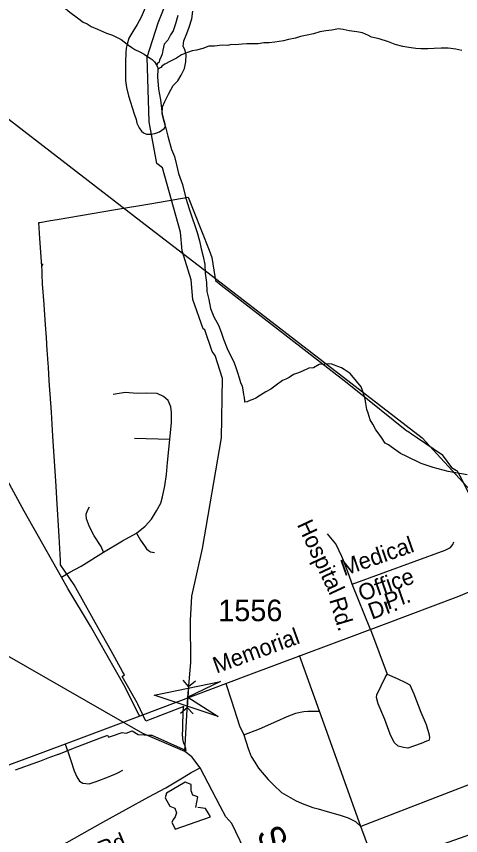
# Model space of a CAD drawing. Extents: x 2260773 to 2342389, y 552869 to 618546.
# Drawn here: x 2309864 to 2312438, y 601248 to 605993 of the extents above; entities that cross this region are included whole.
import ezdxf

# ---------------------------------------------------------------- set-up
doc = ezdxf.new("R2010")
doc.units = 0
for name, color, linetype in [('Exist Boundary Political City Limit New', 7, 'Continuous'), ('Exist Hydrographic Creek Single Shore', 7, 'Continuous'), ('Exist Hydrographic Creek Single Shore Label', 7, 'Continuous'), ('Exist Hydrographic Misc Water Feature', 7, 'Continuous'), ('Exist Road Non-System Type 51', 7, 'Continuous'), ('Exist Road Non-System Type 51 Label', 7, 'Continuous'), ('Exist Road Secondary Structure Culvert Attributed CELL', 7, 'Continuous'), ('Exist Road Secondary Structure Culvert CELL', 7, 'Continuous'), ('Exist Road Secondary Type 51 Attributed', 7, 'Continuous'), ('Exist Road Secondary Type 51 Label', 7, 'Continuous'), ('Exist Road Secondary Type 51 Number Label', 7, 'Continuous'), ('Exist Road Secondary Type 51 Undivided 4 Lane Attributed', 7, 'Continuous'), ('Exist Utilities Electrical Transmission Line', 7, 'Continuous'), ('Map Preparation Boundary City Limit Buffer Line', 7, 'Continuous')]:
    doc.layers.add(name, color=color, linetype=linetype)

msp = doc.modelspace()

# ---------------------------------------------------------------- linework, layer by layer
at = {"layer": 'Exist Boundary Political City Limit New'}
for points in [[(2310013.5, 604550.2), (2310011, 604546.4), (2310000, 604706.4), (2309994, 604798.9), (2310000, 604799.9), (2310061.2, 604810.6), (2310100, 604817.1), (2310235.5, 604839.6), (2310247.5, 604841.6), (2310426.2, 604871.9), (2310649.5, 604909.8), (2310859.5, 604945.5), (2310892, 604862.9), (2310980.5, 604639.3), (2310997.2, 604596.9), (2311014.8, 604486.6), (2311018.5, 604462.6), (2311051.5, 604437), (2311762.8, 603884.8), (2311828.8, 603832.5), (2312117.2, 603600.2), (2312127, 603592.4), (2312131, 603589.9), (2312153.8, 603574.3), (2312188.2, 603551.1), (2312326, 603457.9), (2312329, 603454.9), (2312337.5, 603446.2), (2312385.8, 603381.1), (2312414.8, 603362.3), (2312418.2, 603360.1), (2312426, 603344.6), (2312432.5, 603332), (2312491.2, 603218.5)], [(2310013.5, 604550.2), (2310015, 604555.2), (2310016, 604559.1), (2310016.2, 604559.6)], [(2310016.2, 604559.6), (2310016, 604559.1), (2310015, 604555.2), (2310013.5, 604550.2)], [(2310011, 604541.6), (2310013.5, 604550.2)], [(2310648, 601830.8), (2310848.5, 601742.1), (2310846.8, 601749.4), (2310846, 601754.9), (2310844.2, 601758.4), (2310843.2, 601761.3), (2310842.5, 601764.1), (2310841.5, 601767), (2310840.5, 601769.7), (2310838.8, 601773.4), (2310837.5, 601776.2), (2310836.5, 601778.9), (2310835.2, 601781.7), (2310834.2, 601784.6), (2310833, 601788.3), (2310831.8, 601792.2), (2310831, 601795.1), (2310830.5, 601798.1), (2310830, 601802), (2310829.5, 601805.9), (2310829.2, 601809.4), (2310828.8, 601813.9), (2310828.2, 601817.9), (2310828, 601821.3), (2310827.5, 601826.9), (2310827.2, 601831.4), (2310826.8, 601838.5), (2310827.2, 601843.8), (2310827.5, 601847.8), (2310827.8, 601851.3), (2310828, 601854.8), (2310828.5, 601857.8), (2310828.8, 601861.2), (2310829.2, 601865.2), (2310829.2, 601871.7), (2310829, 601875.7), (2310829, 601879.2), (2310828.8, 601883.7), (2310828.5, 601886.7), (2310828.2, 601893.6), (2310828.5, 601898.7), (2310828.8, 601901.7), (2310829, 601906.3), (2310829, 601909.8), (2310829.2, 601914.7), (2310829.5, 601918.6), (2310829.5, 601922.5), (2310830, 601927.6), (2310830.2, 601931.3), (2310830.5, 601934.2), (2310830.5, 601950.1), (2310830.2, 601953.6), (2310830, 601957.6), (2310830, 601965.6), (2310830.2, 601969.6), (2310830.8, 601975.8), (2310831.5, 601981.5), (2310831.8, 601984.4), (2310832.2, 601987.4), (2310832.5, 601990.9), (2310835, 601996), (2310614, 601912.1), (2310567.8, 602008.9), (2310565.8, 602012.9), (2310563.8, 602016.4), (2310477, 602170.6), (2310491.5, 602178.8), (2310480, 602199.1), (2310413.5, 602318), (2310339, 602450.8), (2310311.8, 602500), (2310198.8, 602701.3), (2310119.2, 602815.7), (2310119.8, 602842.4), (2310111.2, 602980.9), (2310098.2, 603200.6), (2310094, 603271.3), (2310087, 603387.8), (2310076, 603561.8), (2310067.2, 603700.3), (2310063.8, 603751.8), (2310055, 603882.5), (2310049.8, 603960.8), (2310046.8, 604008.2), (2310044.8, 604039.1), (2310043.2, 604058.4), (2310038, 604132.7), (2310033, 604205.7), (2310026.8, 604292.6), (2310026.5, 604297.1), (2310024.8, 604321), (2310024.5, 604324), (2310016.5, 604444), (2310013, 604497.9), (2310012.8, 604522.5), (2310011, 604541.6)], [(2309859.2, 601628.8), (2309987.8, 601675.7), (2310000, 601680.2), (2310059, 601702.8), (2310102.2, 601719.1), (2310106, 601720.2), (2310110, 601720.6), (2310196, 601754.8), (2310215.2, 601762.2), (2310221, 601764.3), (2310351.8, 601813.8), (2310388.5, 601827.7), (2310393, 601829.3), (2310397.5, 601818.5), (2310414.5, 601824.3), (2310477.2, 601845.9), (2310499.8, 601841.6), (2310535.5, 601854.5), (2310570.2, 601834.4), (2310571, 601834.4), (2310637.2, 601830.9), (2310648, 601830.8)]]:
    msp.add_lwpolyline(points, dxfattribs=at)
at = {"layer": 'Exist Hydrographic Creek Single Shore'}
for points in [[(2310839.2, 601735), (2310858.2, 602050.4), (2310875.4, 602251.7), (2310873.2, 602494.4), (2310880.2, 602635.8), (2310943.1, 602910.7), (2311053, 603551.8), (2311058.2, 603896.5), (2311015.1, 604029.3), (2310998.1, 604051.6), (2310955.2, 604177.9), (2310946.2, 604184), (2310886.1, 604352.3), (2310877.1, 604466.7), (2310825.2, 604635.3), (2310815.2, 604743.1), (2310711.2, 605116.3), (2310678.2, 605141.3), (2310633.1, 605382.3), (2310621.2, 605755.9), (2310686.2, 605955.4), (2310953.2, 606625.8)], [(2310839.2, 601735), (2310597.2, 601840), (2309381, 602535.8), (2308987.1, 602831.6), (2308768.1, 603019.6), (2308156.1, 603398.5), (2307938.1, 603570.1), (2307803.2, 603702.5), (2307559.2, 603997.8), (2307415, 604156.1), (2307246, 604379), (2307178.2, 604510.7), (2307169.1, 604579.3), (2307110.1, 604668.8), (2307110.1, 604701.6), (2307093.1, 604727.1), (2307092, 604760), (2307067, 604785.2), (2307040, 604925.2)], [(2311990.9, 599754.9), (2311893.3, 599852.6), (2311820.6, 599965.6), (2311751.1, 600126.2), (2311638.5, 600351.5), (2311550.9, 600489.2), (2311457.1, 600689.5), (2311206.8, 601121.4), (2311112.6, 601319.4), (2311078.4, 601357), (2311044.3, 601418.4), (2310928.3, 601640.4), (2310881.2, 601703.9), (2310839.2, 601735)]]:
    msp.add_lwpolyline(points, dxfattribs=at)
at = {"layer": 'Exist Hydrographic Misc Water Feature'}
msp.add_line((2310728, 605353.5), (2310725.6, 605363.2), dxfattribs=at)
for points in [[(2310914.8, 606896.4), (2310899.2, 606862.3), (2310879.8, 606814.1), (2310856.4, 606765.7), (2310833, 606701.5), (2310800, 606633.5), (2310776.6, 606549), (2310767.6, 606489.2), (2310745.9, 606421), (2310738.9, 606362.9), (2310703.8, 606282.6), (2310690.1, 606238.4), (2310669, 606180), (2310643.3, 606123.8), (2310628, 606081.9), (2310615.9, 606055.8), (2310587.2, 605987.5), (2310563.6, 605945.3), (2310538.2, 605904.9), (2310516.4, 605866.8), (2310506.6, 605832.6)], [(2309889.2, 606377.7), (2309917.7, 606334), (2309963.8, 606274.8), (2310014.9, 606221.3), (2310041.1, 606189.4), (2310073.7, 606135.8), (2310110, 606086.1), (2310136.7, 606048.5), (2310174.8, 606017.1), (2310219.3, 605983.3), (2310251.5, 605959.8), (2310273.6, 605950), (2310297.8, 605934.5), (2310333.9, 605918.6), (2310386, 605895.3), (2310421.9, 605883.8), (2310470.5, 605858.3), (2310506.6, 605832.6)], [(2310798.8, 605997.8), (2310785.2, 605949.6), (2310771.7, 605909.4), (2310758, 605885.1), (2310742.4, 605855), (2310720.4, 605830.8), (2310712.7, 605797.1), (2310709.2, 605772.9), (2310703.2, 605760.8), (2310693.6, 605738.7), (2310691.7, 605726.8), (2310679.6, 605718.5), (2310678, 605708.6)], [(2310845.1, 605780.4), (2310840.8, 605798), (2310830.6, 605820.3), (2310834.7, 605850.1), (2310851.7, 605894.1), (2310865.4, 605930.6), (2310880.6, 605978.6), (2310886.3, 606022.8)], [(2312443.9, 605795.6), (2312409.9, 605803.2), (2312366.2, 605808.5), (2312325.8, 605808.1), (2312284.2, 605805.8), (2312247.9, 605805.2), (2312207.9, 605804.7), (2312178, 605806.8), (2312138.2, 605812), (2312102.1, 605817.8), (2312057.6, 605829.4), (2312019.4, 605844.9), (2311965.9, 605862.3), (2311921.4, 605871.8), (2311903.2, 605881.8), (2311869.1, 605897.1), (2311837, 605902.8), (2311791.2, 605908.5), (2311757.2, 605916), (2311731.1, 605919.9), (2311691.4, 605913.3), (2311656.9, 605908.8), (2311621.4, 605902.4), (2311585.4, 605892.4), (2311549.5, 605884), (2311509.9, 605875.4), (2311481.6, 605867), (2311440, 605858.7), (2311411.7, 605850.4), (2311362.3, 605843.7), (2311328.4, 605839.4), (2311298.1, 605839.1), (2311265.9, 605834.6), (2311234.1, 605834.6), (2311199.9, 605834), (2311172.4, 605831.7), (2311134.2, 605827.3), (2311108.6, 605829.1), (2311088.3, 605824.8), (2311056.3, 605826.4), (2311012.2, 605820.1), (2310978.8, 605819.9), (2310944.8, 605807.2), (2310906.8, 605797), (2310882.8, 605792.5), (2310854.8, 605782.6), (2310845.1, 605780.4)], [(2310506.6, 605832.6), (2310500.8, 605808.7), (2310499.2, 605780.6), (2310496.1, 605728.7), (2310496.7, 605620.7), (2310501.7, 605580.7), (2310514, 605533), (2310547, 605427.4), (2310557.4, 605395.4), (2310561.3, 605373.3), (2310575.9, 605347.6), (2310590, 605327.7), (2310600.3, 605318), (2310618.1, 605310.1), (2310642.3, 605310.5), (2310665.9, 605314.6), (2310693.6, 605325), (2310720, 605343), (2310728, 605353.5)], [(2310506.6, 605832.6), (2310514.6, 605826.9), (2310533, 605812.7), (2310551.1, 605801.1), (2310579.4, 605787.5), (2310605.2, 605773.9), (2310623.7, 605759.8), (2310639.4, 605750.1), (2310651.8, 605742.2), (2310663.6, 605730.2), (2310678, 605708.6)], [(2310845.1, 605780.4), (2310821.3, 605770.2), (2310791.4, 605751.5), (2310757.8, 605733.5), (2310724.1, 605715), (2310707.9, 605706.9), (2310702, 605696.9), (2310684.1, 605686.6)], [(2310725.6, 605363.2), (2310723.6, 605371.3), (2310718.9, 605390.3), (2310709.6, 605428.5), (2310710.4, 605468.9), (2310724.3, 605499.3), (2310745.9, 605541.5), (2310773.3, 605591.6), (2310798.8, 605619.8), (2310818.7, 605652.1), (2310837.7, 605690.2), (2310845.7, 605730.4), (2310847.2, 605772.3), (2310845.1, 605780.4)], [(2310678, 605708.6), (2310684.1, 605694.7), (2310684.1, 605686.6)], [(2310684.1, 605686.6), (2310682.7, 605642.6), (2310687.4, 605570.9), (2310698.3, 605508.9), (2310706.5, 605441.1), (2310709.6, 605428.5), (2310718.9, 605390.3), (2310723.6, 605371.3), (2310725.6, 605363.2)], [(2310728, 605353.5), (2310742.2, 605299.5), (2310763.1, 605221.7), (2310779.5, 605182), (2310792, 605132.2), (2310802.9, 605082.3), (2310827.1, 605018.6), (2310845.9, 604940.8), (2310864.6, 604879.1), (2310882.8, 604825.3), (2310897.6, 604781.3), (2310912.4, 604741.4), (2310924.7, 604693.7), (2310935.1, 604645.9), (2310945.6, 604602.2), (2310955.8, 604556), (2310958.5, 604506.2), (2310964.9, 604452.4), (2310967.9, 604398.5), (2310978.6, 604352.7), (2310989.1, 604300.8), (2311007.3, 604253), (2311036, 604205.3), (2311050.4, 604163.4), (2311064.9, 604123.5), (2311085.2, 604069.8), (2311099.4, 604040.1), (2311122.3, 603996), (2311132.4, 603970.2), (2311144.5, 603930.7), (2311154.9, 603898.7), (2311163.4, 603872.6), (2311171.8, 603850.8), (2311177.9, 603819), (2311180.4, 603800.8), (2311184.1, 603785.2), (2311186.3, 603765), (2311186.5, 603759.3)], [(2312476.3, 603337.2), (2312366.4, 603357.8), (2312278, 603380.9), (2312209.9, 603404), (2312125.5, 603443.2), (2312089, 603460.8), (2312062.9, 603480.5), (2312034.8, 603500.2), (2312020.5, 603512.1), (2312000.6, 603522), (2311978.6, 603553.7), (2311960, 603581.6), (2311945.8, 603599.2), (2311929.4, 603631.2), (2311913.2, 603656.8), (2311903, 603694.8), (2311894.4, 603716.8), (2311888.2, 603750.6), (2311883.9, 603778.4), (2311869.4, 603826.4), (2311861.1, 603848.3), (2311834.9, 603879.9), (2311798.2, 603925.5), (2311762.3, 603947.1), (2311748.2, 603957), (2311726.2, 603964.8), (2311707.8, 603972.4), (2311691.8, 603978.5), (2311669.6, 603980.1), (2311650.2, 603977.8), (2311618, 603975.8), (2311586.4, 603957), (2311557.9, 603954.8), (2311526.1, 603940.5), (2311498.6, 603928.5), (2311470.5, 603918.1), (2311444.9, 603901.7), (2311425, 603891.3), (2311405.3, 603883.3), (2311369.4, 603857.1), (2311337.7, 603834.7), (2311310, 603818.2), (2311278.4, 603799.8), (2311251.9, 603781.9), (2311234.5, 603773.6), (2311216.5, 603767.3), (2311200.5, 603761.2), (2311186.5, 603759.3)], [(2308855.1, 600275.9), (2309019.5, 600219.5), (2309127.4, 600234.9), (2309413, 600461.7), (2309636.9, 600632.3), (2309800.6, 600867.6), (2309961.5, 601099.3), (2310365.2, 601326.2), (2310631.4, 601473.1), (2310730.3, 601524.3), (2310836.1, 601589.2), (2310877.1, 601613.1), (2310928.3, 601640.4)], [(2310842.9, 601558.5), (2310733.7, 601493.6), (2310726.9, 601466.3), (2310754.2, 601418.4), (2310781.5, 601408.2), (2310791.8, 601380.9), (2310784.9, 601357), (2310774.7, 601343.3), (2310764.5, 601326.2), (2310784.9, 601285.3), (2310989.7, 601357), (2310976, 601380.9), (2310959, 601404.8), (2310914.6, 601411.6)], [(2310877.1, 601544.8), (2310842.9, 601558.5)], [(2310904.4, 601411.6), (2310914.6, 601473.1), (2310887.3, 601483.3), (2310877.1, 601507.2), (2310877.1, 601544.8)]]:
    msp.add_lwpolyline(points, dxfattribs=at)
at = {"layer": 'Exist Road Non-System Type 51'}
for p, q in [((2310752.8, 603542.4), (2310549.5, 603547.3)), ((2310125.1, 602745.4), (2310174.7, 602773.1)), ((2310124.8, 602745.2), (2310125.1, 602745.4)), ((2311914.9, 602442.5), (2311808.5, 602704.5)), ((2311914.9, 602442.5), (2312012.3, 602183)), ((2311620.3, 601968.8), (2311504, 602292.4)), ((2311860.4, 601301.1), (2311620.3, 601968.8)), ((2310147.2, 601778.1), (2310163.4, 601729.4)), ((2310163.4, 601729.4), (2310165.3, 601723.7)), ((2312693.2, 601623), (2311860.4, 601301.1))]:
    msp.add_line(p, q, dxfattribs=at)
for points in [[(2310762.3, 603699.2), (2310759.4, 603730.9), (2310742.9, 603768.9), (2310716.4, 603792.1), (2310680.1, 603808.6), (2310615.6, 603810.3), (2310564.4, 603808.6), (2310495, 603813.6), (2310425.6, 603802)], [(2310752.8, 603542.4), (2310762.7, 603639.9), (2310762.7, 603694.5), (2310762.3, 603699.2)], [(2310561.1, 602999.9), (2310610.7, 603041.3), (2310647, 603081), (2310676.8, 603128.9), (2310701.6, 603173.6), (2310711.5, 603210), (2310724.7, 603274.5), (2310733, 603338.9), (2310739.6, 603410.1), (2310752.8, 603542.4)], [(2310369.4, 602890.8), (2310354.5, 602922.2), (2310314.8, 602985), (2310288.4, 603036.3), (2310270.2, 603082.6), (2310268.5, 603109.1), (2310276.8, 603130.6), (2310288.4, 603152.1)], [(2310369.4, 602890.8), (2310478.4, 602955.3), (2310561.1, 602999.9)], [(2310561.1, 602999.9), (2310582.6, 602960.2), (2310605.7, 602927.2), (2310618.9, 602909), (2310628.8, 602899), (2310642.1, 602892.4), (2310665.2, 602887.5)], [(2311749.7, 602864.2), (2311715, 602938.6), (2311666.4, 602996.1)], [(2311808.5, 602704.5), (2312348, 602902.1), (2312379.3, 602917.8), (2312393.2, 602935.2), (2312398.4, 602949.2)], [(2310174.7, 602773.1), (2310240.4, 602809.7), (2310369.4, 602890.8)], [(2311808.5, 602704.5), (2311790.8, 602759.7), (2311755.9, 602851.1), (2311749.7, 602864.2)], [(2312012.3, 602183), (2312070.5, 602159.1), (2312118.2, 602135.3), (2312143.4, 602122), (2312165.9, 602069), (2312208.2, 601963), (2312237.4, 601891.5), (2312255.9, 601831.9), (2312257.7, 601815.3), (2312253.3, 601800.1), (2312241, 601794.8), (2312209.3, 601782.5), (2312131.4, 601755.7), (2312106.3, 601759), (2312075.8, 601765.6), (2312052, 601786.8), (2312029.5, 601835.8), (2311999, 601920.6), (2311960.5, 602012), (2311951.3, 602047.8), (2311952.7, 602063.7), (2311976.5, 602115.4), (2312000.4, 602164.4), (2312012.3, 602183)], [(2311076.7, 602130.1), (2311110.7, 602029.8), (2311157.7, 601883.5), (2311182.1, 601833)], [(2311182.1, 601833), (2311272.6, 601866.1), (2311373.5, 601911.4), (2311432.7, 601937.5), (2311483.1, 601956.7), (2311507.5, 601963.6), (2311530.1, 601967.1), (2311552.7, 601968.8), (2311570.1, 601968.8), (2311592.8, 601968.8), (2311620.3, 601968.8)], [(2311182.1, 601833), (2311206.4, 601752.9), (2311223.9, 601705.9), (2311244.7, 601672.8), (2311267.4, 601639.8), (2311300.4, 601599.7), (2311323, 601573.6), (2311356.1, 601540.5), (2311399.6, 601498.7), (2311441.4, 601474.3), (2311481.4, 601451.7), (2311519.7, 601434.3), (2311582.3, 601411.7), (2311611.6, 601404), (2311663.8, 601388.3), (2311740.1, 601367.5), (2311785.9, 601350.7), (2311829.4, 601329.8), (2311860.4, 601301.1)], [(2310165.3, 601723.7), (2310178.8, 601683.4), (2310198.2, 601623.2), (2310214.2, 601589.5), (2310230.1, 601562.9), (2310249.6, 601552.3), (2310286.8, 601548.8), (2310325.7, 601561.2), (2310398.3, 601589.5), (2310447.9, 601610.8), (2310481.5, 601626.7)], [(2312693.2, 601623), (2312764.7, 601410.4), (2312772.6, 601382.6), (2312776.6, 601362.7), (2312768.6, 601346.8), (2312697.2, 601320.9), (2312587.9, 601287.2), (2311993, 601076.6), (2311968.9, 601072.4), (2311958.9, 601074.2), (2311950.9, 601078.1), (2311928.4, 601113.8), (2311860.4, 601301.1)]]:
    msp.add_lwpolyline(points, dxfattribs=at)
at = {"layer": 'Exist Road Secondary Structure Culvert Attributed CELL'}
msp.add_lwpolyline([(2311034.1, 601937.7), (2310662.6, 602062.6), (2311046.8, 602140.2), (2310858.2, 602050.4)], close=True, dxfattribs=at)
at = {"layer": 'Exist Road Secondary Structure Culvert CELL'}
for p, q in [((2310827.8, 602148), (2310862.3, 602110.7)), ((2310901.4, 602143.1), (2310862.3, 602110.7)), ((2310862.3, 602110.7), (2310854.2, 601990)), ((2310815, 601957.7), (2310854.2, 601990)), ((2310888.6, 601952.7), (2310854.2, 601990))]:
    msp.add_line(p, q, dxfattribs=at)
at = {"layer": 'Exist Road Secondary Type 51 Attributed'}
msp.add_lwpolyline([(2310578.7, 601940.1), (2310573.6, 601950.2), (2310486.5, 602121.9), (2310292.9, 602461.6), (2310162.7, 602680.2), (2310125.2, 602744.5), (2310124.8, 602745.2), (2309909.1, 603128.1), (2309801.6, 603325.7), (2309671.1, 603550.6), (2309532.2, 603802), (2309434.7, 603969), (2309363.9, 604092.8), (2309260, 604273.6), (2309199, 604360.8), (2309112.4, 604486.7), (2308988.5, 604643.8), (2308816.1, 604852.4), (2308676, 605037), (2308578.8, 605159.9), (2308493.7, 605260.9), (2308428.2, 605347.5), (2308377, 605426)], dxfattribs=at)
at = {"layer": 'Exist Road Secondary Type 51 Undivided 4 Lane Attributed'}
for points in [[(2314675.4, 605551.6), (2314096.8, 604646), (2313585.2, 603885.9), (2313262.6, 603420.1), (2312980.3, 603028.2), (2312934.1, 602964.1), (2312760.4, 602799.4), (2312627.3, 602718.4), (2312426.3, 602632.2), (2311995.6, 602470.3), (2311208.3, 602177.7), (2310578.7, 601940.1)], [(2310578.7, 601940.1), (2310147.2, 601778.1), (2309950.1, 601704.2), (2309839.4, 601663.2), (2309672.1, 601601.3), (2309638.3, 601588.8), (2309616, 601580.5), (2309341, 601484.8), (2309316.5, 601477), (2308961.7, 601354.2), (2308924, 601341.2), (2308725, 601272.3), (2308612.5, 601230.9), (2308427.5, 601162.7), (2308208.2, 601086), (2307972.6, 600994.2)]]:
    msp.add_lwpolyline(points, dxfattribs=at)
at = {"layer": 'Exist Utilities Electrical Transmission Line'}
for p, q in [((2309431.5, 605696.2), (2310585.5, 604806.9)), ((2310585.5, 604806.9), (2311000, 604487.4))]:
    msp.add_line(p, q, dxfattribs=at)
msp.add_lwpolyline([(2311000, 604487.4), (2312214.1, 603551.8), (2312473.1, 603270.6), (2312535.5, 603206.5)], dxfattribs=at)
at = {"layer": 'Map Preparation Boundary City Limit Buffer Line'}
for points in [[(2310013.5, 604550.2), (2310011, 604546.4), (2310000, 604706.4), (2309994, 604798.9), (2310000, 604799.9), (2310061.2, 604810.6), (2310100, 604817.1), (2310235.5, 604839.6), (2310247.5, 604841.6), (2310426.2, 604871.9), (2310649.5, 604909.8), (2310859.5, 604945.5), (2310892, 604862.9), (2310980.5, 604639.3), (2310997.2, 604596.9), (2311014.8, 604486.6), (2311018.5, 604462.6), (2311051.5, 604437), (2311762.8, 603884.8), (2311828.8, 603832.5), (2312117.2, 603600.2), (2312127, 603592.4), (2312131, 603589.9), (2312153.8, 603574.3), (2312188.2, 603551.1), (2312326, 603457.9), (2312329, 603454.9), (2312337.5, 603446.2), (2312385.8, 603381.1), (2312414.8, 603362.3), (2312418.2, 603360.1), (2312426, 603344.6), (2312432.5, 603332), (2312491.2, 603218.5)], [(2310013.5, 604550.2), (2310015, 604555.2), (2310016, 604559.1), (2310016.2, 604559.6)], [(2310016.2, 604559.6), (2310016, 604559.1), (2310015, 604555.2), (2310013.5, 604550.2)], [(2310011, 604541.6), (2310013.5, 604550.2)], [(2310648, 601830.8), (2310848.5, 601742.1), (2310846.8, 601749.4), (2310846, 601754.9), (2310844.2, 601758.4), (2310843.2, 601761.3), (2310842.5, 601764.1), (2310841.5, 601767), (2310840.5, 601769.7), (2310838.8, 601773.4), (2310837.5, 601776.2), (2310836.5, 601778.9), (2310835.2, 601781.7), (2310834.2, 601784.6), (2310833, 601788.3), (2310831.8, 601792.2), (2310831, 601795.1), (2310830.5, 601798.1), (2310830, 601802), (2310829.5, 601805.9), (2310829.2, 601809.4), (2310828.8, 601813.9), (2310828.2, 601817.9), (2310828, 601821.3), (2310827.5, 601826.9), (2310827.2, 601831.4), (2310826.8, 601838.5), (2310827.2, 601843.8), (2310827.5, 601847.8), (2310827.8, 601851.3), (2310828, 601854.8), (2310828.5, 601857.8), (2310828.8, 601861.2), (2310829.2, 601865.2), (2310829.2, 601871.7), (2310829, 601875.7), (2310829, 601879.2), (2310828.8, 601883.7), (2310828.5, 601886.7), (2310828.2, 601893.6), (2310828.5, 601898.7), (2310828.8, 601901.7), (2310829, 601906.3), (2310829, 601909.8), (2310829.2, 601914.7), (2310829.5, 601918.6), (2310829.5, 601922.5), (2310830, 601927.6), (2310830.2, 601931.3), (2310830.5, 601934.2), (2310830.5, 601950.1), (2310830.2, 601953.6), (2310830, 601957.6), (2310830, 601965.6), (2310830.2, 601969.6), (2310830.8, 601975.8), (2310831.5, 601981.5), (2310831.8, 601984.4), (2310832.2, 601987.4), (2310832.5, 601990.9), (2310835, 601996), (2310614, 601912.1), (2310567.8, 602008.9), (2310565.8, 602012.9), (2310563.8, 602016.4), (2310477, 602170.6), (2310491.5, 602178.8), (2310480, 602199.1), (2310413.5, 602318), (2310339, 602450.8), (2310311.8, 602500), (2310198.8, 602701.3), (2310119.2, 602815.7), (2310119.8, 602842.4), (2310111.2, 602980.9), (2310098.2, 603200.6), (2310094, 603271.3), (2310087, 603387.8), (2310076, 603561.8), (2310067.2, 603700.3), (2310063.8, 603751.8), (2310055, 603882.5), (2310049.8, 603960.8), (2310046.8, 604008.2), (2310044.8, 604039.1), (2310043.2, 604058.4), (2310038, 604132.7), (2310033, 604205.7), (2310026.8, 604292.6), (2310026.5, 604297.1), (2310024.8, 604321), (2310024.5, 604324), (2310016.5, 604444), (2310013, 604497.9), (2310012.8, 604522.5), (2310011, 604541.6)], [(2309859.2, 601628.8), (2309987.8, 601675.7), (2310000, 601680.2), (2310059, 601702.8), (2310102.2, 601719.1), (2310106, 601720.2), (2310110, 601720.6), (2310196, 601754.8), (2310215.2, 601762.2), (2310221, 601764.3), (2310351.8, 601813.8), (2310388.5, 601827.7), (2310393, 601829.3), (2310397.5, 601818.5), (2310414.5, 601824.3), (2310477.2, 601845.9), (2310499.8, 601841.6), (2310535.5, 601854.5), (2310570.2, 601834.4), (2310571, 601834.4), (2310637.2, 601830.9), (2310648, 601830.8)]]:
    msp.add_lwpolyline(points, dxfattribs=at)

# ---------------------------------------------------------------- texts
at = {"layer": 'Exist Hydrographic Creek Single Shore Label'}
msp.add_text('Stony', height=150, rotation=296.7288, dxfattribs=at).set_placement((2311251.1, 601260.1))
at = {"layer": 'Exist Road Non-System Type 51 Label'}
for s, rotation, p in [('Hospital', 295.0522, (2311488.1, 603050.2)), ('Medical', 19.1958, (2311762.4, 602750)), ('Office', 19.1958, (2311864.1, 602603.5)), ('Pl.', 19.1958, (2312016.8, 602555.4)), ('Rd.', 286.6601, (2311675.6, 602614.3)), ('Rd.', 22.0378, (2310359, 601119.5))]:
    msp.add_text(s, height=95, rotation=rotation, dxfattribs=at).set_placement(p)
at = {"layer": 'Exist Road Secondary Type 51 Label'}
for s, rotation, p in [('Dr.', 20.1177, (2311923.3, 602498.3)), ('Memorial', 19.962, (2311023.1, 602186.1))]:
    msp.add_text(s, height=95, rotation=rotation, dxfattribs=at).set_placement(p)
at = {"layer": 'Exist Road Secondary Type 51 Number Label'}
msp.add_text('1556', height=125, dxfattribs=at).set_placement((2311033.5, 602490.1))

doc.saveas('drawing.dxf')
